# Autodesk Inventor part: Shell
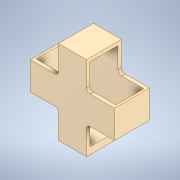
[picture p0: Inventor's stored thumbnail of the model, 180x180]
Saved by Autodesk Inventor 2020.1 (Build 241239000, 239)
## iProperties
Created: 2019-10
Part Number: Shell
Material: Polyethylene, Low Density
Document SubType Name: Modeling
Designer: Synergysoft Dell02
Density: 0.894 g/cm^3
Appearance: Smooth - Off-White
Author: Synergysoft Dell02
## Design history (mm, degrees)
sketch "Sketch1"
  geometry: L1 (-20, 60)-(20, 60); L2 (20, 60)-(20, -60); L3 (20, -60)-(-20, -60); L4 (-20, -60)-(-20, 60); L5 (-20, 60)-(20, -60); L6 (20, 60)-(-20, -60); L7 (-60, 20)-(60, 20); L8 (60, 20)-(60, -20); L9 (60, -20)-(-60, -20); L10 (-60, -20)-(-60, 20); L11 (-60, 20)-(60, -20); L12 (60, 20)-(-60, -20); 5 further points
  constraints: 24 end point, 4 midpoint, 4 parallel, 2 horizontal, 2 perpendicular
  dimensions: "d0" = 40 distance of L2.end L3.end; "d1" = 120 distance of L1.end L2.end (= d2); "d2" = 120 distance of L8.end L9.end; "d3" = 40 distance of L7.end L8.end (= d0)
extrude "Extrusion1" new body sketch "Sketch1" stored distance "d4" = 50; taper "d5" = 0 deg
fillet "Fillet1" dims "d7" = 5
shell "Shell1" dims "d6" = 5, "d8" = 10, "d9" = 3
body "Solid1"
